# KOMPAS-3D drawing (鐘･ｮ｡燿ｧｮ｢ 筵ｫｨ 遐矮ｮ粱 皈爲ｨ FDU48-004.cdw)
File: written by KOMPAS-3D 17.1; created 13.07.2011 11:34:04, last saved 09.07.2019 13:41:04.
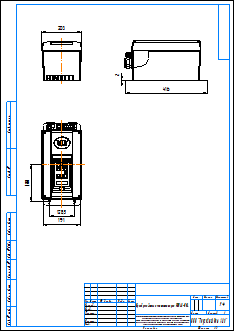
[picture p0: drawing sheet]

Title block, sheet 1: name: Преобразователи частоты серии FDU48-004; scale: 1:4; sheets: 1; sheet format: A3; stored path: \\adlc.lan\data\АДЛ_ПКД\3D-модели\Поставщики\Оборудование Emotron\Преобразователи частоты\Серия FDU 2.0\KOMPAS 2D\Преобразователи частоты серии FDU48-004.cdw

Views: Спереди 1
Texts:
  Рама для чертежей
  Лит-Масса-Масштаб
  Материал-Предприятие
  Масштаб
  Изм.
  Лист
  № докум.
  Подп.
  Дата
  Лит.
  Разраб.
  Пров.
  Т.контр.
  Листов
  Внимание! Данный продукт является объектом авторского права ООО «Торговый Дом АДЛ».
  Запрещается изменение, копирование, распространение
  (в том числе путем копирования на другие сайты и ресурсы в Интернете)
  или любое иное использование информации и объектов без предварительного
  согласия правообладателя (ООО «Торговый Дом АДЛ»).
  Н.контр.
  Утв.
  ООО "Торговый дом АДЛ"
  Изменение
  Номер документа
  Подпись
  Обозначение документа
  Наименование изделия
  Масса изделия по ГОСТ 2.109-73
  Порядковый номер листа
  Общее количество листов в документе
  Характер работы, выполненной лицом, подписавшим документ
  Наименование или индекс предприятия, выпускающего документ
  Инв. № подл.
  Подп. и дата
  Взам. инв. №
  Инв. № дубл.
  Инвентарный номер подлинника по ГОСТ 2.501-68
  Подпись принявшего подлинник в отдел технической документации
  Инвентарный номер подлинника, взамен которого выпущен данный подлинник
  Инвентарный номер дубликата по ГОСТ 2.502-68
  Подпись принявшего дубликат в отдел технической документации
  Справ. №
  Перв. примен.
  Обозначение документа, взамен или на основании которого выпущен данный документ
  Обозначение документа, в котором впервые записан данный документ
  Подпись лица, копировавшего чертеж
  Обозначение формата листа
  !Рама для чертежа
Dimensions and other numbers on the sheet: 203; 416; 128,5; 191; 188; 2; 1:4; 1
